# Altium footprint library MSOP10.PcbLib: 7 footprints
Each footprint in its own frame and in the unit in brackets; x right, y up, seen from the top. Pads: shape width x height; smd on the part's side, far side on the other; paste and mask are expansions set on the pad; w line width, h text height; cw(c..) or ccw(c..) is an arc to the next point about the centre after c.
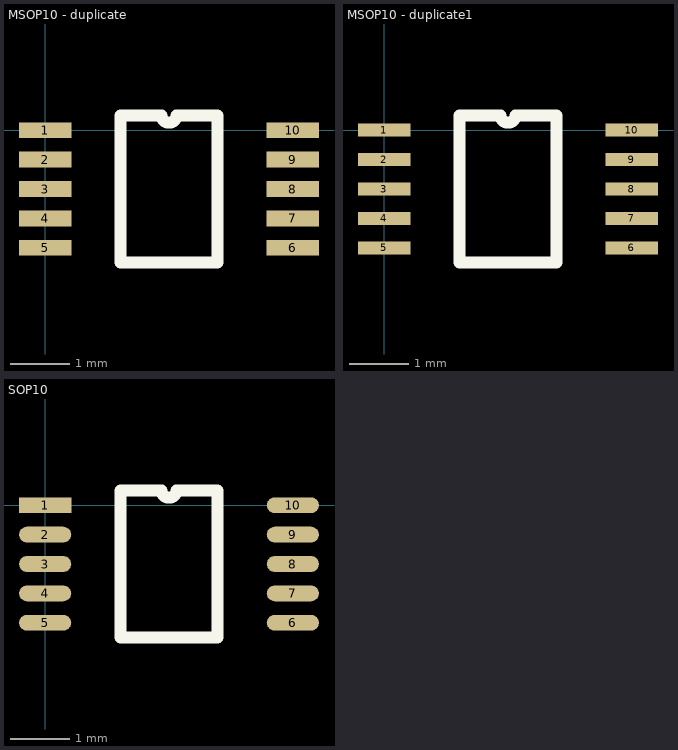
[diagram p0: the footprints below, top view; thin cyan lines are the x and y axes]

## MSOP10 [mil]

## MSOP10 - duplicate [mil]
pads (10):
  rect 35x10.51 smd: 1(0,0) 2(0,-19.68) 3(0,-39.37) 4(0,-59.05) 5(0,-78.74) 6(165.79,-78.74) 7(165.79,-59.05) 8(165.79,-39.37) 9(165.79,-19.68) 10(165.79,0)
Top Overlay:
  lines w7.87: 50.37,-88.58 115.41,-88.58 115.41,9.84 87.81,9.84 cw(c82.89,9.84) 77.97,9.84 50.37,9.84 50.37,-88.58

## MSOP10 - duplicate1 [mm]
pads (10):
  rect 0.889x0.22 smd: 1(0,0) 2(0,-0.5) 3(0,-1) 4(0,-1.5) 5(0,-2) 6(4.211,-2) 7(4.211,-1.5) 8(4.211,-1) 9(4.211,-0.5) 10(4.211,0)
Top Overlay:
  lines w0.2: 1.279,-2.25 2.932,-2.25 2.932,0.25 2.23,0.25 cw(c2.105,0.25) 1.981,0.25 1.279,0.25 1.279,-2.25

## MSOP-10 [mil]

## MSOP-10 - duplicate [mil]

## PCBComponent_1 [mil]

## SOP10 [mil]
pads (10):
  rect 35x10.51 smd: 1(0,0)
  oval 35x10.51 smd: 2(0,-19.68) 3(0,-39.37) 4(0,-59.05) 5(0,-78.74) 6(165.79,-78.74) 7(165.79,-59.05) 8(165.79,-39.37) 9(165.79,-19.68) 10(165.79,0)
Top Overlay:
  lines w7.87: 50.37,-88.58 50.37,9.84 77.97,9.84 ccw(c82.89,9.84) 87.81,9.84 115.41,9.84 115.41,-88.58 50.37,-88.58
